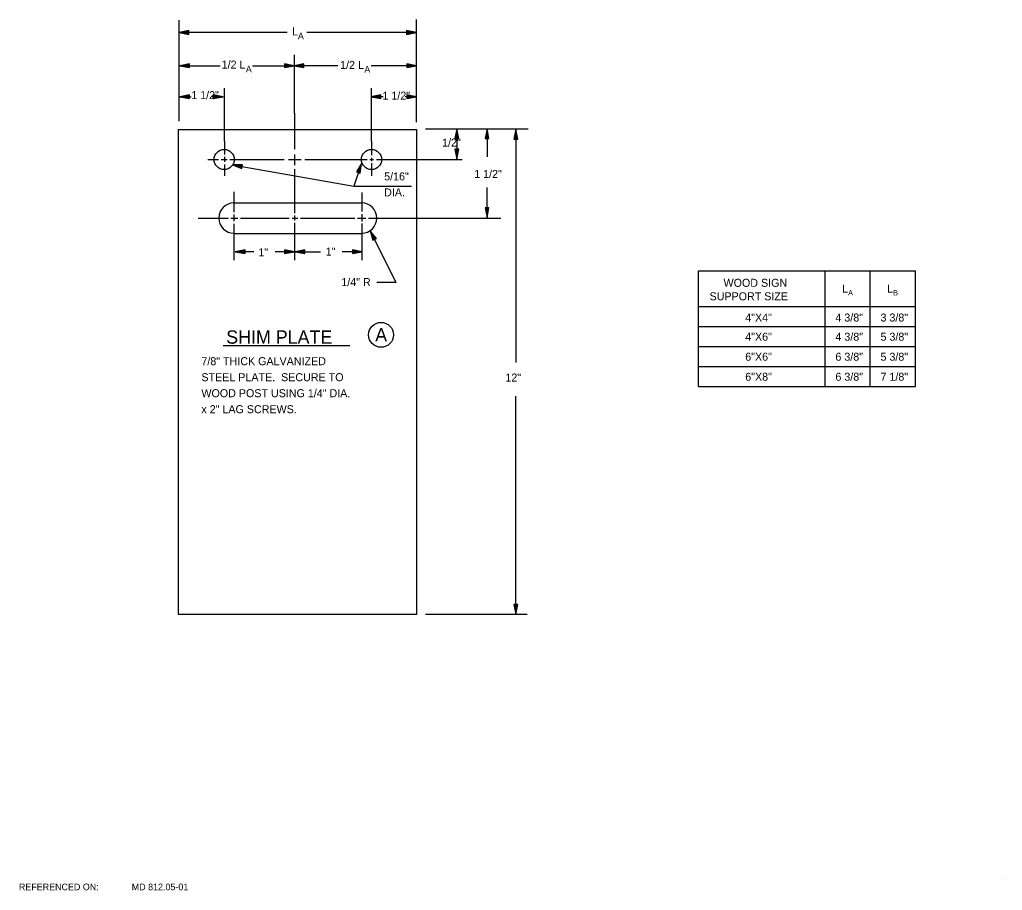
# Model space of a CAD drawing. Extents: x 51.3 to 58.6, y 21.9 to 32.
# Drawn here: x 51.25 to 58.62, y 21.91 to 28.43 of the extents above; entities that cross this region are included whole.
import ezdxf

# ---------------------------------------------------------------- set-up
doc = ezdxf.new("R2010")
doc.units = 0
for name, color, linetype in [('DETL-DIMS', 7, 'Continuous'), ('DETL-LINE', 7, 'Continuous'), ('DETL-NOTE', 7, 'Continuous'), ('DETL-TITL', 7, 'Continuous'), ('TTLB-TEXT', 7, 'Continuous')]:
    doc.layers.add(name, color=color, linetype=linetype)

msp = doc.modelspace()

# ---------------------------------------------------------------- linework, layer by layer
at = {"layer": 'DETL-DIMS'}
for p, q in [((52.4463, 27.6694), (52.4463, 28.4264)), ((54.2263, 27.6621), (54.2263, 28.4311)), ((53.2575, 28.3344), (52.4463, 28.3344)), ((54.2263, 28.3344), (53.4026, 28.3344)), ((53.3123, 27.7294), (53.3123, 28.1684)), ((52.4513, 28.0844), (52.7548, 28.0844)), ((52.9964, 28.0844), (53.3123, 28.0844)), ((53.636, 28.0844), (53.3123, 28.0844)), ((54.2241, 28.0844), (53.8858, 28.0844)), ((52.4513, 27.8534), (52.5356, 27.8534)), ((52.7753, 27.8534), (52.6909, 27.8534)), ((52.7853, 27.5194), (52.7853, 27.9174)), ((53.975, 27.8534), (53.8843, 27.8534)), ((53.8883, 27.5194), (53.8883, 27.9174)), ((54.2263, 27.8534), (54.1406, 27.8534)), ((53.3123, 27.7294), (53.3123, 27.4604)), ((54.2933, 27.6134), (55.0633, 27.6134)), ((54.5283, 27.6134), (54.5283, 27.3854)), ((54.7543, 27.6134), (54.7543, 27.4034)), ((54.9703, 27.6094), (54.9703, 25.9394)), ((52.7853, 27.5194), (52.7853, 27.4214)), ((53.8883, 27.5194), (53.8883, 27.4144)), ((53.3123, 27.4214), (53.3123, 27.3404)), ((52.6613, 27.3824), (52.7413, 27.3824)), ((52.7623, 27.3824), (52.8063, 27.3824)), ((52.7853, 27.4024), (52.7853, 27.3654)), ((52.7853, 27.3454), (52.7853, 27.2594)), ((52.8253, 27.3824), (53.2343, 27.3824)), ((52.8475, 27.3419), (53.7563, 27.1844)), ((53.2653, 27.3824), (53.3613, 27.3824)), ((53.3883, 27.3824), (53.8563, 27.3824)), ((53.8133, 27.3534), (53.7563, 27.1844)), ((53.8753, 27.3824), (53.9023, 27.3824)), ((53.8883, 27.3954), (53.8883, 27.3694)), ((53.8883, 27.3544), (53.8883, 27.2594)), ((53.9263, 27.3824), (54.0163, 27.3824)), ((54.0163, 27.3824), (54.5693, 27.3824)), ((53.3123, 27.3114), (53.3123, 26.9814)), ((53.7563, 27.1844), (54.1873, 27.1844)), ((52.8573, 27.1404), (52.8573, 26.9894)), ((53.8153, 27.1354), (53.8153, 26.9944)), ((54.7543, 26.9474), (54.7543, 27.1734)), ((52.8573, 26.9714), (52.8573, 26.9204)), ((53.3123, 26.9644), (53.3123, 26.9264)), ((53.8153, 26.9744), (53.8153, 26.9194)), ((52.5883, 26.9434), (52.8163, 26.9434)), ((52.8333, 26.9434), (52.8873, 26.9434)), ((52.8573, 26.9014), (52.8573, 26.7564)), ((52.9073, 26.9434), (53.2713, 26.9434)), ((53.2933, 26.9434), (53.3373, 26.9434)), ((53.3123, 26.9074), (53.3123, 26.6284)), ((53.3573, 26.9434), (53.7633, 26.9434)), ((53.7833, 26.9434), (53.8463, 26.9434)), ((53.8153, 26.9024), (53.8153, 26.7264)), ((53.8663, 26.9434), (54.1023, 26.9434)), ((54.1023, 26.9434), (54.8573, 26.9434)), ((53.8793, 26.8494), (54.0713, 26.4604)), ((52.8573, 26.7564), (52.8573, 26.6274)), ((53.0053, 26.6914), (52.8663, 26.6914)), ((53.3103, 26.6914), (53.1663, 26.6914)), ((53.3153, 26.6914), (53.5053, 26.6914)), ((53.8173, 26.6914), (53.6693, 26.6914)), ((53.8153, 26.7264), (53.8153, 26.6274)), ((54.0713, 26.4604), (53.9283, 26.4604)), ((54.9703, 25.9394), (54.9703, 25.8604)), ((54.9703, 25.4944), (54.9703, 25.6084)), ((54.9703, 23.9744), (54.9703, 25.4944)), ((54.2933, 23.9744), (55.0543, 23.9744))]:
    msp.add_line(p, q, dxfattribs=at)
for points in [[(52.5203, 28.3494), (52.4463, 28.3344), (52.5203, 28.3204), (52.5203, 28.3494)], [(52.5173, 28.3474), (52.4563, 28.3344), (52.5173, 28.3234), (52.5173, 28.3474)], [(52.5163, 28.3444), (52.4663, 28.3344), (52.5163, 28.3254), (52.5163, 28.3444)], [(52.5153, 28.3424), (52.4743, 28.3344), (52.5153, 28.3284), (52.5153, 28.3424)], [(52.5133, 28.3394), (52.4853, 28.3344), (52.5133, 28.3294), (52.5133, 28.3394)], [(52.5113, 28.3374), (52.4943, 28.3344), (52.5113, 28.3314), (52.5113, 28.3374)], [(52.5103, 28.3364), (52.5033, 28.3344), (52.5103, 28.3344), (52.5103, 28.3364)], [(54.1513, 28.3204), (54.2263, 28.3344), (54.1513, 28.3494), (54.1513, 28.3204)], [(54.1543, 28.3234), (54.2163, 28.3344), (54.1543, 28.3474), (54.1543, 28.3234)], [(54.1563, 28.3254), (54.2063, 28.3344), (54.1563, 28.3444), (54.1563, 28.3254)], [(54.1583, 28.3284), (54.1963, 28.3344), (54.1583, 28.3424), (54.1583, 28.3284)], [(54.1603, 28.3294), (54.1873, 28.3344), (54.1603, 28.3394), (54.1603, 28.3294)], [(54.1623, 28.3314), (54.1783, 28.3344), (54.1623, 28.3374), (54.1623, 28.3314)], [(54.1633, 28.3344), (54.1673, 28.3344), (54.1633, 28.3364), (54.1633, 28.3344)], [(52.5243, 28.0994), (52.4513, 28.0844), (52.5243, 28.0714), (52.5243, 28.0994)], [(52.5233, 28.0974), (52.4603, 28.0844), (52.5233, 28.0724), (52.5233, 28.0974)], [(52.5203, 28.0944), (52.4703, 28.0844), (52.5203, 28.0744), (52.5203, 28.0944)], [(52.5193, 28.0934), (52.4793, 28.0844), (52.5193, 28.0774), (52.5193, 28.0934)], [(52.5163, 28.0904), (52.4893, 28.0844), (52.5163, 28.0794), (52.5163, 28.0904)], [(52.5163, 28.0884), (52.4993, 28.0844), (52.5163, 28.0814), (52.5163, 28.0884)], [(52.5133, 28.0854), (52.5083, 28.0844), (52.5133, 28.0834), (52.5133, 28.0854)], [(53.2353, 28.0714), (53.3083, 28.0844), (53.2353, 28.0994), (53.2353, 28.0714)], [(53.2363, 28.0724), (53.2983, 28.0844), (53.2363, 28.0974), (53.2363, 28.0724)], [(53.2393, 28.0744), (53.2883, 28.0844), (53.2393, 28.0944), (53.2393, 28.0744)], [(53.2403, 28.0774), (53.2803, 28.0844), (53.2403, 28.0934), (53.2403, 28.0774)], [(53.2423, 28.0794), (53.2713, 28.0844), (53.2423, 28.0904), (53.2423, 28.0794)], [(53.2443, 28.0814), (53.2613, 28.0844), (53.2443, 28.0884), (53.2443, 28.0814)], [(53.2463, 28.0834), (53.2513, 28.0844), (53.2463, 28.0854), (53.2463, 28.0834)], [(53.3813, 28.0994), (53.3083, 28.0844), (53.3813, 28.0714), (53.3813, 28.0994)], [(53.3803, 28.0974), (53.3173, 28.0844), (53.3803, 28.0724), (53.3803, 28.0974)], [(53.3773, 28.0944), (53.3273, 28.0844), (53.3773, 28.0744), (53.3773, 28.0944)], [(53.3763, 28.0934), (53.3363, 28.0844), (53.3763, 28.0774), (53.3763, 28.0934)], [(53.3733, 28.0904), (53.3463, 28.0844), (53.3733, 28.0794), (53.3733, 28.0904)], [(53.3733, 28.0884), (53.3563, 28.0844), (53.3733, 28.0814), (53.3733, 28.0884)], [(53.3703, 28.0854), (53.3653, 28.0844), (53.3703, 28.0834), (53.3703, 28.0854)], [(54.1529, 28.0714), (54.2259, 28.0844), (54.1529, 28.0994), (54.1529, 28.0714)], [(54.1539, 28.0724), (54.2159, 28.0844), (54.1539, 28.0974), (54.1539, 28.0724)], [(54.1569, 28.0744), (54.2059, 28.0844), (54.1569, 28.0944), (54.1569, 28.0744)], [(54.1579, 28.0774), (54.1979, 28.0844), (54.1579, 28.0934), (54.1579, 28.0774)], [(54.1599, 28.0794), (54.1889, 28.0844), (54.1599, 28.0904), (54.1599, 28.0794)], [(54.1619, 28.0814), (54.1789, 28.0844), (54.1619, 28.0884), (54.1619, 28.0814)], [(54.1639, 28.0834), (54.1689, 28.0844), (54.1639, 28.0854), (54.1639, 28.0834)], [(52.5243, 27.8674), (52.4513, 27.8534), (52.5243, 27.8394), (52.5243, 27.8674)], [(52.5233, 27.8644), (52.4603, 27.8534), (52.5233, 27.8414), (52.5233, 27.8644)], [(52.5203, 27.8624), (52.4703, 27.8534), (52.5203, 27.8444), (52.5203, 27.8624)], [(52.5193, 27.8594), (52.4793, 27.8534), (52.5193, 27.8454), (52.5193, 27.8594)], [(52.5163, 27.8584), (52.4893, 27.8534), (52.5163, 27.8464), (52.5163, 27.8584)], [(52.5163, 27.8554), (52.4993, 27.8534), (52.5163, 27.8494), (52.5163, 27.8554)], [(52.5133, 27.8544), (52.5083, 27.8534), (52.5133, 27.8524), (52.5133, 27.8544)], [(52.7023, 27.8394), (52.7753, 27.8534), (52.7023, 27.8674), (52.7023, 27.8394)], [(52.7043, 27.8414), (52.7663, 27.8534), (52.7043, 27.8644), (52.7043, 27.8414)], [(52.7063, 27.8444), (52.7553, 27.8534), (52.7063, 27.8624), (52.7063, 27.8444)], [(52.7063, 27.8454), (52.7473, 27.8534), (52.7063, 27.8594), (52.7063, 27.8454)], [(52.7093, 27.8464), (52.7373, 27.8534), (52.7093, 27.8584), (52.7093, 27.8464)], [(52.7113, 27.8494), (52.7273, 27.8534), (52.7113, 27.8554), (52.7113, 27.8494)], [(52.7133, 27.8524), (52.7183, 27.8534), (52.7133, 27.8544), (52.7133, 27.8524)], [(53.9583, 27.8674), (53.8843, 27.8534), (53.9583, 27.8394), (53.9583, 27.8674)], [(53.9573, 27.8644), (53.8943, 27.8534), (53.9573, 27.8414), (53.9573, 27.8644)], [(53.9553, 27.8624), (53.9043, 27.8534), (53.9553, 27.8444), (53.9553, 27.8624)], [(53.9533, 27.8594), (53.9133, 27.8534), (53.9533, 27.8454), (53.9533, 27.8594)], [(53.9513, 27.8584), (53.9233, 27.8534), (53.9513, 27.8464), (53.9513, 27.8584)], [(53.9503, 27.8554), (53.9323, 27.8534), (53.9503, 27.8494), (53.9503, 27.8554)], [(53.9473, 27.8544), (53.9423, 27.8534), (53.9473, 27.8524), (53.9473, 27.8544)], [(54.1533, 27.8394), (54.2263, 27.8534), (54.1533, 27.8674), (54.1533, 27.8394)], [(54.1543, 27.8414), (54.2163, 27.8534), (54.1543, 27.8644), (54.1543, 27.8414)], [(54.1573, 27.8444), (54.2073, 27.8534), (54.1573, 27.8624), (54.1573, 27.8444)], [(54.1583, 27.8454), (54.1993, 27.8534), (54.1583, 27.8594), (54.1583, 27.8454)], [(54.1603, 27.8464), (54.1893, 27.8534), (54.1603, 27.8584), (54.1603, 27.8464)], [(54.1623, 27.8494), (54.1793, 27.8534), (54.1623, 27.8554), (54.1623, 27.8494)], [(54.1643, 27.8524), (54.1693, 27.8534), (54.1643, 27.8544), (54.1643, 27.8524)], [(54.5433, 27.5404), (54.5283, 27.6134), (54.5143, 27.5404), (54.5433, 27.5404)], [(54.5413, 27.5424), (54.5283, 27.6044), (54.5163, 27.5424), (54.5413, 27.5424)], [(54.5383, 27.5444), (54.5283, 27.5944), (54.5193, 27.5444), (54.5383, 27.5444)], [(54.5363, 27.5454), (54.5283, 27.5854), (54.5213, 27.5454), (54.5363, 27.5454)], [(54.5333, 27.5484), (54.5283, 27.5754), (54.5233, 27.5484), (54.5333, 27.5484)], [(54.5313, 27.5494), (54.5283, 27.5664), (54.5263, 27.5494), (54.5313, 27.5494)], [(54.5303, 27.5514), (54.5283, 27.5564), (54.5283, 27.5514), (54.5303, 27.5514)], [(54.7683, 27.5404), (54.7543, 27.6134), (54.7413, 27.5404), (54.7683, 27.5404)], [(54.7663, 27.5424), (54.7543, 27.6044), (54.7413, 27.5424), (54.7663, 27.5424)], [(54.7643, 27.5444), (54.7543, 27.5944), (54.7453, 27.5444), (54.7643, 27.5444)], [(54.7633, 27.5454), (54.7543, 27.5854), (54.7473, 27.5454), (54.7633, 27.5454)], [(54.7603, 27.5484), (54.7543, 27.5754), (54.7503, 27.5484), (54.7603, 27.5484)], [(54.7573, 27.5494), (54.7543, 27.5664), (54.7513, 27.5494), (54.7573, 27.5494)], [(54.7553, 27.5514), (54.7543, 27.5564), (54.7523, 27.5514), (54.7553, 27.5514)], [(54.9843, 27.5354), (54.9703, 27.6094), (54.9563, 27.5354), (54.9843, 27.5354)], [(54.9813, 27.5384), (54.9703, 27.5994), (54.9573, 27.5384), (54.9813, 27.5384)], [(54.9793, 27.5394), (54.9703, 27.5904), (54.9603, 27.5394), (54.9793, 27.5394)], [(54.9783, 27.5424), (54.9703, 27.5804), (54.9623, 27.5424), (54.9783, 27.5424)], [(54.9763, 27.5434), (54.9703, 27.5714), (54.9653, 27.5434), (54.9763, 27.5434)], [(54.9733, 27.5454), (54.9703, 27.5604), (54.9673, 27.5454), (54.9733, 27.5454)], [(54.9713, 27.5464), (54.9703, 27.5514), (54.9693, 27.5464), (54.9713, 27.5464)], [(54.5143, 27.4594), (54.5283, 27.3854), (54.5433, 27.4594), (54.5143, 27.4594)], [(54.5163, 27.4584), (54.5283, 27.3954), (54.5413, 27.4584), (54.5163, 27.4584)], [(54.5193, 27.4554), (54.5283, 27.4044), (54.5383, 27.4554), (54.5193, 27.4554)], [(54.5213, 27.4544), (54.5283, 27.4144), (54.5363, 27.4544), (54.5213, 27.4544)], [(54.5233, 27.4524), (54.5283, 27.4244), (54.5333, 27.4524), (54.5233, 27.4524)], [(54.5263, 27.4504), (54.5283, 27.4344), (54.5313, 27.4504), (54.5263, 27.4504)], [(54.5283, 27.4484), (54.5283, 27.4444), (54.5303, 27.4484), (54.5283, 27.4484)], [(52.9225, 27.3429), (52.8475, 27.3419), (52.9175, 27.3159), (52.9225, 27.3429)], [(52.9205, 27.3419), (52.8565, 27.3409), (52.9165, 27.3179), (52.9205, 27.3419)], [(52.9185, 27.3399), (52.8665, 27.3399), (52.9155, 27.3209), (52.9185, 27.3399)], [(52.9165, 27.3389), (52.8765, 27.3369), (52.9135, 27.3229), (52.9165, 27.3389)], [(52.9135, 27.3369), (52.8845, 27.3369), (52.9115, 27.3269), (52.9135, 27.3369)], [(52.9115, 27.3349), (52.8955, 27.3339), (52.9105, 27.3289), (52.9115, 27.3349)], [(52.9095, 27.3319), (52.9045, 27.3319), (52.9095, 27.3319), (52.9095, 27.3319)], [(53.8033, 27.2794), (53.8133, 27.3534), (53.7763, 27.2894), (53.8033, 27.2794)], [(53.8013, 27.2814), (53.8113, 27.3444), (53.7793, 27.2894), (53.8013, 27.2814)], [(53.8003, 27.2844), (53.8063, 27.3344), (53.7813, 27.2894), (53.8003, 27.2844)], [(53.7993, 27.2864), (53.8043, 27.3264), (53.7833, 27.2904), (53.7993, 27.2864)], [(53.7973, 27.2894), (53.8013, 27.3164), (53.7863, 27.2924), (53.7973, 27.2894)], [(53.7963, 27.2904), (53.7973, 27.3084), (53.7903, 27.2934), (53.7963, 27.2904)], [(53.7943, 27.2934), (53.7953, 27.2984), (53.7923, 27.2944), (53.7943, 27.2934)], [(54.7413, 27.0214), (54.7543, 26.9474), (54.7683, 27.0214), (54.7413, 27.0214)], [(54.7413, 27.0194), (54.7543, 26.9574), (54.7663, 27.0194), (54.7413, 27.0194)], [(54.7453, 27.0174), (54.7543, 26.9664), (54.7643, 27.0174), (54.7453, 27.0174)], [(54.7473, 27.0164), (54.7543, 26.9754), (54.7633, 27.0164), (54.7473, 27.0164)], [(54.7503, 27.0144), (54.7543, 26.9864), (54.7603, 27.0144), (54.7503, 27.0144)], [(54.7513, 27.0124), (54.7543, 26.9954), (54.7573, 27.0124), (54.7513, 27.0124)], [(54.7523, 27.0094), (54.7543, 27.0044), (54.7553, 27.0094), (54.7523, 27.0094)], [(53.9253, 26.7904), (53.8793, 26.8494), (53.8993, 26.7794), (53.9253, 26.7904)], [(53.9223, 26.7904), (53.8833, 26.8424), (53.9003, 26.7814), (53.9223, 26.7904)], [(53.9203, 26.7924), (53.8883, 26.8334), (53.9013, 26.7834), (53.9203, 26.7924)], [(53.9163, 26.7934), (53.8913, 26.8244), (53.9023, 26.7854), (53.9163, 26.7934)], [(53.9133, 26.7934), (53.8963, 26.8154), (53.9043, 26.7884), (53.9133, 26.7934)], [(53.9113, 26.7944), (53.9003, 26.8084), (53.9053, 26.7904), (53.9113, 26.7944)], [(53.9073, 26.7944), (53.9053, 26.7994), (53.9063, 26.7934), (53.9073, 26.7944)], [(52.9413, 26.7054), (52.8663, 26.6914), (52.9413, 26.6784), (52.9413, 26.7054)], [(52.9403, 26.7044), (52.8763, 26.6914), (52.9403, 26.6794), (52.9403, 26.7044)], [(52.9373, 26.7014), (52.8863, 26.6914), (52.9373, 26.6824), (52.9373, 26.7014)], [(52.9363, 26.7004), (52.8963, 26.6914), (52.9363, 26.6844), (52.9363, 26.7004)], [(52.9333, 26.6984), (52.9063, 26.6914), (52.9333, 26.6874), (52.9333, 26.6984)], [(52.9323, 26.6944), (52.9153, 26.6914), (52.9323, 26.6894), (52.9323, 26.6944)], [(52.9303, 26.6924), (52.9253, 26.6914), (52.9303, 26.6894), (52.9303, 26.6924)], [(53.2363, 26.6784), (53.3103, 26.6914), (53.2363, 26.7054), (53.2363, 26.6784)], [(53.2393, 26.6794), (53.3013, 26.6914), (53.2393, 26.7044), (53.2393, 26.6794)], [(53.2403, 26.6824), (53.2913, 26.6914), (53.2403, 26.7014), (53.2403, 26.6824)], [(53.2423, 26.6844), (53.2813, 26.6914), (53.2423, 26.7004), (53.2423, 26.6844)], [(53.2443, 26.6874), (53.2713, 26.6914), (53.2443, 26.6984), (53.2443, 26.6874)], [(53.2463, 26.6894), (53.2613, 26.6914), (53.2463, 26.6944), (53.2463, 26.6894)], [(53.2463, 26.6894), (53.2523, 26.6914), (53.2463, 26.6924), (53.2463, 26.6894)], [(53.3883, 26.7054), (53.3153, 26.6914), (53.3883, 26.6784), (53.3883, 26.7054)], [(53.3863, 26.7044), (53.3253, 26.6914), (53.3863, 26.6794), (53.3863, 26.7044)], [(53.3863, 26.7014), (53.3353, 26.6914), (53.3863, 26.6824), (53.3863, 26.7014)], [(53.3833, 26.7004), (53.3423, 26.6914), (53.3833, 26.6844), (53.3833, 26.7004)], [(53.3813, 26.6984), (53.3533, 26.6914), (53.3813, 26.6874), (53.3813, 26.6984)], [(53.3793, 26.6944), (53.3623, 26.6914), (53.3793, 26.6894), (53.3793, 26.6944)], [(53.3783, 26.6924), (53.3713, 26.6914), (53.3783, 26.6894), (53.3783, 26.6924)], [(53.7453, 26.6784), (53.8173, 26.6914), (53.7453, 26.7054), (53.7453, 26.6784)], [(53.7463, 26.6794), (53.8083, 26.6914), (53.7463, 26.7044), (53.7463, 26.6794)], [(53.7493, 26.6824), (53.7993, 26.6914), (53.7493, 26.7014), (53.7493, 26.6824)], [(53.7503, 26.6844), (53.7903, 26.6914), (53.7503, 26.7004), (53.7503, 26.6844)], [(53.7513, 26.6874), (53.7813, 26.6914), (53.7513, 26.6984), (53.7513, 26.6874)], [(53.7533, 26.6894), (53.7703, 26.6914), (53.7533, 26.6944), (53.7533, 26.6894)], [(53.7563, 26.6894), (53.7613, 26.6914), (53.7563, 26.6924), (53.7563, 26.6894)], [(54.9563, 24.0484), (54.9703, 23.9744), (54.9843, 24.0484), (54.9563, 24.0484)], [(54.9573, 24.0474), (54.9703, 23.9844), (54.9813, 24.0474), (54.9573, 24.0474)], [(54.9603, 24.0444), (54.9703, 23.9944), (54.9793, 24.0444), (54.9603, 24.0444)], [(54.9623, 24.0444), (54.9703, 24.0044), (54.9783, 24.0444), (54.9623, 24.0444)], [(54.9653, 24.0414), (54.9703, 24.0134), (54.9763, 24.0414), (54.9653, 24.0414)], [(54.9673, 24.0404), (54.9703, 24.0234), (54.9733, 24.0404), (54.9673, 24.0404)], [(54.9693, 24.0384), (54.9703, 24.0334), (54.9713, 24.0384), (54.9693, 24.0384)]]:
    msp.add_lwpolyline(points, dxfattribs=at)
at = {"layer": 'DETL-LINE'}
for p, q in [((52.4403, 27.6074), (52.4403, 23.9764)), ((52.4403, 27.6074), (54.2283, 27.6074)), ((54.2283, 23.9764), (54.2283, 27.6074)), ((52.8573, 27.0574), (53.8153, 27.0574)), ((52.8573, 26.8294), (53.8153, 26.8294)), ((52.4403, 23.9764), (54.2283, 23.9764))]:
    msp.add_line(p, q, dxfattribs=at)
for centre in [(52.7839, 27.3831), (53.8883, 27.3831)]:
    msp.add_circle(centre, 0.0757, dxfattribs=at)
for centre, start, end in [((52.8573, 26.9441), 90, 270), ((53.8148, 26.9441), 270, 90)]:
    msp.add_arc(centre, 0.1136, start, end, dxfattribs=at)
at = {"layer": 'DETL-NOTE'}
for p, q in [((56.3385, 26.5494), (57.9658, 26.5494)), ((56.3385, 25.6808), (56.3385, 26.5494)), ((57.2898, 25.6808), (57.2898, 26.5494)), ((57.6278, 25.6808), (57.6278, 26.5494)), ((57.9658, 25.6808), (57.9658, 26.5494)), ((56.3385, 26.2808), (57.9658, 26.2808)), ((56.3385, 26.1308), (57.9658, 26.1308)), ((56.3385, 25.9808), (57.9658, 25.9808)), ((56.3385, 25.8308), (57.9658, 25.8308)), ((56.3385, 25.6808), (57.9658, 25.6808))]:
    msp.add_line(p, q, dxfattribs=at)
msp.add_circle((53.9605, 26.0689), 0.0934, dxfattribs=at)
at = {"layer": 'DETL-TITL'}
msp.add_line((52.7772, 25.9895), (53.7252, 25.9895), dxfattribs=at)
at = {"layer": 'TTLB-TEXT'}
msp.add_line((58.6174, 21.9876), (58.6174, 21.9876), dxfattribs=at)

# ---------------------------------------------------------------- texts
at = {"layer": 'DETL-NOTE'}
for s, height, p in [('L', 0.06, (53.2923, 28.313)), ('A', 0.05, (53.3363, 28.2844)), ('1/2 L', 0.06, (52.7652, 28.0644)), ('A', 0.05, (52.9465, 28.0357)), ('1/2 L', 0.06, (53.6532, 28.062)), ('A', 0.05, (53.8346, 28.0333)), ('1 1/2"', 0.06, (52.537, 27.8354)), ('1 1/2"', 0.06, (53.9704, 27.8319)), ('5/16"', 0.06, (53.9833, 27.2264)), ('DIA.', 0.06, (53.9833, 27.1064)), ('1"', 0.06, (53.0403, 26.6574)), ('1"', 0.06, (53.5453, 26.6634)), ('1/4" R', 0.06, (53.6622, 26.4344)), ('WOOD SIGN', 0.06, (56.5274, 26.4288)), ('SUPPORT SIZE', 0.06, (56.4225, 26.3278)), ('L', 0.06, (57.4165, 26.3851)), ('A', 0.04, (57.461, 26.3642)), ('L', 0.06, (57.7545, 26.3851)), ('B', 0.04, (57.799, 26.3642)), ('4"X4"', 0.06, (56.6901, 26.1686)), ('4 3/8"', 0.06, (57.366, 26.1686)), ('3 3/8"', 0.06, (57.704, 26.1686)), ('A', 0.1, (53.9163, 26.0194)), ('4"X6"', 0.06, (56.6901, 26.0249)), ('4 3/8"', 0.06, (57.366, 26.0249)), ('5 3/8"', 0.06, (57.704, 26.0249)), ('6"X6"', 0.06, (56.6901, 25.8749)), ('6 3/8"', 0.06, (57.366, 25.8749)), ('5 3/8"', 0.06, (57.704, 25.8749)), ('7/8" THICK GALVANIZED', 0.06, (52.6133, 25.8414)), ('6"X8"', 0.06, (56.6901, 25.7249)), ('6 3/8"', 0.06, (57.366, 25.7249)), ('7 1/8"', 0.06, (57.704, 25.7249)), ('STEEL PLATE.  SECURE TO', 0.06, (52.6133, 25.7214)), ('WOOD POST USING 1/4" DIA.', 0.06, (52.6133, 25.6014)), ('x 2" LAG SCREWS.', 0.06, (52.6133, 25.4814))]:
    msp.add_text(s, height=height, dxfattribs=at).set_placement(p)
for s, p in [('1/2"', (54.4175, 27.4798)), ('1 1/2"', (54.6584, 27.2448)), ('12"', (54.8922, 25.7188))]:
    msp.add_text(s, height=0.06, rotation=360, dxfattribs=at).set_placement(p)
at = {"layer": 'DETL-TITL'}
msp.add_text('SHIM PLATE', height=0.1, dxfattribs=at).set_placement((52.7993, 26.0024))
at = {"layer": 'TTLB-TEXT'}
for s, p in [('REFERENCED ON:', (51.2454, 21.9062)), ('MD 812.05-01', (52.0913, 21.9062))]:
    msp.add_text(s, height=0.05, rotation=360, dxfattribs=at).set_placement(p)

doc.saveas('drawing.dxf')
